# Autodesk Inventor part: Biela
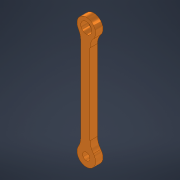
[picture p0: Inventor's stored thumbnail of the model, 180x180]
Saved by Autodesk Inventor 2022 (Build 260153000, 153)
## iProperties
Created: 2021-08
Part Number: Biela
Material: Gold
Document SubType Name: Modeling
Designer: user
Density: 19.3 g/cm^3
Appearance: Metal 1600F Hot
Mass: 0.450204 g
Surface Area: 0.929028 cm^2
Volume: 0.0233266 cm^3
Author: user
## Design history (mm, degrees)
sketch "Sketch1" dims "d2" = 1
  geometry: L1 (6.821, 3.749)-(8.071, 3.749); L2 (8.071, 3.749)-(8.071, -11.251); L3 (8.071, -11.251)-(6.821, -11.251); L4 (6.821, -11.251)-(6.821, 3.749); C1 r 0.75 at (7.571, 3.749) reference; C2 r 1.25 at (7.571, 3.749); C3 r 1.25 at (7.571, -11.251); 7 further points
  constraints: 8 end point, 3 coincident, 2 centre point, 2 horizontal alignment, 2 parallel, 1 horizontal, 1 perpendicular, 5 other
  dimensions: "d0" = 2.5 diameter of C2; "d1" = 2.5 diameter of C3; "d3" = 15 distance of C3.centre C1.centre
extrude "Extrusion1" new body sketch "Sketch1" distance "d4" = 1; taper "d5" = 0 deg
fillet "Fillet1" dims "d6" = 2
body "Solid1"
node "Reference1"
